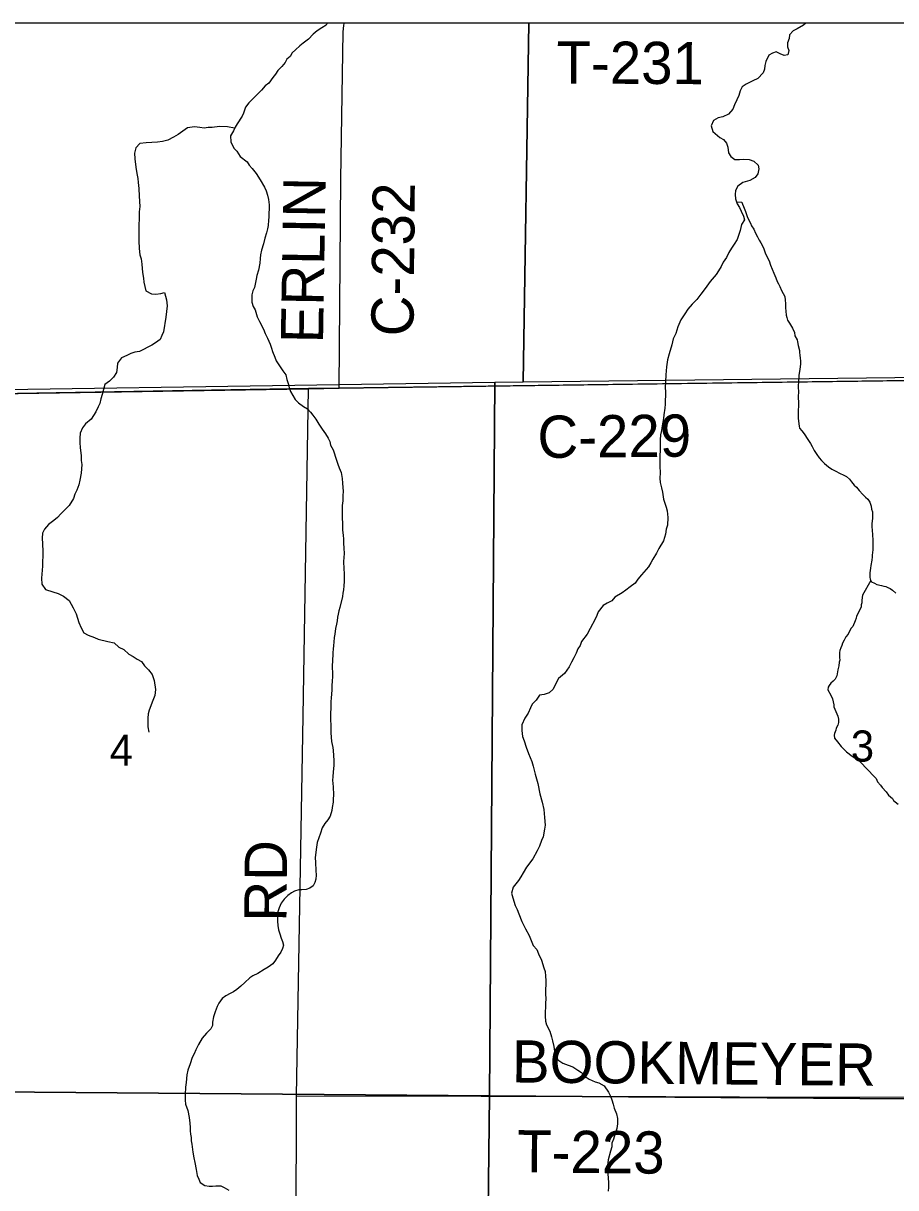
# Model space of a CAD drawing. Extents: x 0 to 34, y 0 to 22.
# Drawn here: x 4.9 to 6.074, y 19.332 to 20.9 of the extents above; entities that cross this region are included whole.
import ezdxf

# ---------------------------------------------------------------- set-up
doc = ezdxf.new("R2010")
doc.units = 0
for name, color, linetype in [('Default', 7, 'Continuous'), ('GM_X_County_Road', 7, 'Continuous'), ('GM_X_County_Road_Text', 7, 'Continuous'), ('GM_X_Minor_River', 7, 'Continuous'), ('GM_X_Section', 7, 'Continuous'), ('GM_X_Section_Text', 7, 'Continuous'), ('GM_X_Township', 7, 'Continuous'), ('GM_X_Township_Road', 7, 'Continuous'), ('GM_X_Township_Road_Text', 7, 'Continuous'), ('SH_Cut_Line', 7, 'Continuous')]:
    doc.layers.add(name, color=color, linetype=linetype)

msp = doc.modelspace()

# ---------------------------------------------------------------- linework, layer by layer
at = {"layer": 'Default'}
for points in [[(5.5805, 20.9), (4.5809, 20.9), (4.5765, 20.4024), (5.5347, 20.4166), (5.573, 20.4171)], [(6.5742, 20.9), (5.5805, 20.9), (5.573, 20.4171), (6.5354, 20.4284), (6.5611, 20.4294)]]:
    msp.add_lwpolyline(points, close=True, dxfattribs=at)
at = {"layer": 'GM_X_County_Road'}
for p, q in [((5.3252, 20.4086), (5.7863, 20.4148)), ((4.5786, 20.3962), (5.2548, 20.4076)), ((5.2548, 20.4076), (5.2842, 20.408)), ((5.2767, 19.9672), (5.2842, 20.408)), ((5.2842, 20.408), (5.3252, 20.4086))]:
    msp.add_line(p, q, dxfattribs=at)
for points in [[(5.3252, 20.4086), (5.3278, 20.69), (5.3306, 20.8882), (5.3315, 20.8973), (5.3319, 20.8992), (5.3321, 20.9)], [(5.7863, 20.4148), (6.5318, 20.4249), (6.5577, 20.4253)], [(5.2631, 18.9836), (5.2634, 18.9924), (5.2647, 19.0793), (5.2659, 19.1795), (5.2671, 19.291), (5.2679, 19.3886), (5.2681, 19.4561), (5.2767, 19.9672)]]:
    msp.add_lwpolyline(points, dxfattribs=at)
at = {"layer": 'GM_X_Minor_River'}
for points in [[(5.3092, 20.9), (5.3078, 20.8975), (5.302, 20.8938), (5.2959, 20.8897), (5.2906, 20.8855), (5.284, 20.8788), (5.2768, 20.8732), (5.2726, 20.8698), (5.2668, 20.8642), (5.2622, 20.86), (5.2595, 20.8551), (5.2549, 20.8518), (5.2526, 20.8472), (5.2483, 20.842), (5.2426, 20.8363), (5.2399, 20.8314), (5.236, 20.8269), (5.2306, 20.8194), (5.226, 20.8156), (5.2207, 20.81), (5.2145, 20.8036), (5.2088, 20.798), (5.2038, 20.7927), (5.1992, 20.7871), (5.1968, 20.7791), (5.1948, 20.775), (5.1879, 20.7648), (5.1852, 20.7603), (5.1832, 20.755), (5.179, 20.7486), (5.1797, 20.7402), (5.1837, 20.7318), (5.1875, 20.7276), (5.192, 20.7207), (5.2017, 20.7134), (5.2043, 20.7088), (5.2085, 20.7046), (5.2137, 20.6977), (5.2189, 20.6893), (5.2249, 20.6794), (5.2271, 20.6744), (5.2289, 20.6687), (5.2304, 20.6626), (5.231, 20.6554), (5.2309, 20.6391), (5.2304, 20.6349), (5.2296, 20.6277), (5.2288, 20.6231), (5.2276, 20.6178), (5.2252, 20.6106), (5.2236, 20.6031), (5.2209, 20.5944), (5.2197, 20.5883), (5.2192, 20.5834), (5.2184, 20.5769), (5.2168, 20.5678), (5.2144, 20.5603), (5.2136, 20.5553), (5.2124, 20.5489), (5.2112, 20.5444), (5.2092, 20.5398), (5.2077, 20.5345), (5.2079, 20.5247), (5.2098, 20.5189), (5.2124, 20.514), (5.2149, 20.5048), (5.2183, 20.4987), (5.2234, 20.488), (5.226, 20.4823), (5.229, 20.4762), (5.2323, 20.4678), (5.2342, 20.4625), (5.2356, 20.4579), (5.2389, 20.4503), (5.2408, 20.4457), (5.2497, 20.432), (5.2538, 20.4266), (5.2549, 20.4205), (5.2571, 20.4137), (5.2582, 20.4091), (5.26, 20.4041), (5.266, 20.3934), (5.2705, 20.3888), (5.2773, 20.3842), (5.2829, 20.3807), (5.287, 20.3765), (5.29, 20.3723), (5.2938, 20.367), (5.2978, 20.3601), (5.3027, 20.3536), (5.3072, 20.3471), (5.3105, 20.3413), (5.3128, 20.3371), (5.3135, 20.3318), (5.3172, 20.3257), (5.322, 20.312), (5.3234, 20.3063), (5.3253, 20.3017)], [(5.9534, 20.9), (5.9504, 20.8974), (5.9416, 20.8926), (5.9362, 20.89), (5.9316, 20.8844), (5.9308, 20.8794), (5.9289, 20.8738), (5.9288, 20.8684), (5.9306, 20.8635), (5.929, 20.8574), (5.9241, 20.8567), (5.9188, 20.8587), (5.9135, 20.8614), (5.9086, 20.8599), (5.9036, 20.857), (5.8997, 20.8486), (5.8982, 20.8433), (5.8977, 20.8384), (5.8958, 20.8331), (5.8889, 20.8256), (5.882, 20.8226), (5.8732, 20.8178), (5.8679, 20.8144), (5.8651, 20.8092), (5.8632, 20.8027), (5.8605, 20.7967), (5.8573, 20.7903), (5.855, 20.7842), (5.8492, 20.7774), (5.8416, 20.7741), (5.8355, 20.7726), (5.829, 20.7693), (5.8259, 20.7617), (5.8281, 20.7541), (5.8375, 20.7464), (5.8428, 20.7437), (5.8465, 20.7384), (5.8483, 20.733), (5.8494, 20.7254), (5.8524, 20.7205), (5.858, 20.7166), (5.8641, 20.7165), (5.8694, 20.7172), (5.877, 20.7164), (5.8834, 20.7144), (5.8894, 20.7091), (5.8901, 20.7041), (5.8889, 20.6973), (5.8854, 20.6924), (5.8782, 20.6883), (5.8687, 20.6854), (5.8618, 20.6809), (5.8587, 20.6748), (5.8582, 20.6695), (5.8589, 20.6638), (5.8611, 20.657), (5.8641, 20.652), (5.8663, 20.647), (5.8697, 20.6402), (5.8708, 20.6352), (5.8669, 20.6292), (5.8649, 20.6209), (5.861, 20.6088), (5.8571, 20.6027), (5.8532, 20.5971), (5.8498, 20.5914), (5.8467, 20.5846), (5.842, 20.5782), (5.8397, 20.5725), (5.8358, 20.5665), (5.8327, 20.5616), (5.8247, 20.5522), (5.8181, 20.5428), (5.812, 20.5353), (5.8066, 20.5281), (5.8004, 20.5217), (5.7947, 20.5153), (5.7904, 20.5089)], [(5.1846, 20.7587), (5.175, 20.7607), (5.1643, 20.7609), (5.1545, 20.7598), (5.1492, 20.7595), (5.1435, 20.7588), (5.1378, 20.7596), (5.1306, 20.7605), (5.1211, 20.7594), (5.115, 20.7546), (5.1088, 20.7504), (5.1023, 20.7467), (5.0947, 20.7426), (5.0875, 20.7408), (5.0807, 20.7401), (5.0731, 20.7394), (5.0655, 20.7391), (5.0571, 20.7381), (5.0517, 20.7321), (5.0501, 20.7253), (5.0504, 20.7177), (5.0518, 20.7063), (5.0532, 20.6979), (5.0543, 20.6911), (5.055, 20.6854), (5.0557, 20.6774), (5.0563, 20.6671), (5.0569, 20.6531), (5.0564, 20.6462), (5.0563, 20.6371), (5.0559, 20.628), (5.0556, 20.6071), (5.0563, 20.5969), (5.0573, 20.5881), (5.0588, 20.5828), (5.0598, 20.5756), (5.0608, 20.5646), (5.0619, 20.557), (5.0626, 20.5513), (5.0636, 20.5456), (5.0651, 20.5399), (5.0726, 20.5356), (5.0787, 20.5352), (5.0852, 20.5362), (5.0905, 20.5377), (5.093, 20.5278), (5.0937, 20.5194), (5.092, 20.5043), (5.0891, 20.4846), (5.0868, 20.4796), (5.0844, 20.4744), (5.0783, 20.4699), (5.0734, 20.4665), (5.0566, 20.4583), (5.0505, 20.4573), (5.0448, 20.4554), (5.0394, 20.4528), (5.0326, 20.4495), (5.0272, 20.4423), (5.0264, 20.4366), (5.0255, 20.4298), (5.0217, 20.4234), (5.0163, 20.4181), (5.0098, 20.4137), (5.0062, 20.4), (5.0046, 20.3944), (5.0034, 20.3883), (5.0011, 20.3834), (4.998, 20.377), (4.9918, 20.3672), (4.9838, 20.3608), (4.9799, 20.3555), (4.9768, 20.348), (4.9763, 20.3415), (4.9763, 20.3354), (4.9766, 20.3286), (4.978, 20.3183), (4.9783, 20.3115), (4.979, 20.3058), (4.9781, 20.2944), (4.9765, 20.2849), (4.9752, 20.2785), (4.9721, 20.2713), (4.9698, 20.266), (4.9678, 20.26), (4.962, 20.2509), (4.9563, 20.2449), (4.9509, 20.2397), (4.9463, 20.2348), (4.9413, 20.2307), (4.934, 20.2254), (4.9287, 20.219), (4.9259, 20.2134), (4.9255, 20.2069), (4.9262, 20.1993), (4.9264, 20.1887), (4.9262, 20.1689), (4.9249, 20.153), (4.9252, 20.1447), (4.93, 20.1378), (4.9402, 20.1346)], [(5.8603, 20.6595), (5.8674, 20.6593), (5.8682, 20.6563), (5.8697, 20.6533), (5.8724, 20.6465), (5.8743, 20.64), (5.8766, 20.6347), (5.8789, 20.6309), (5.8805, 20.6275), (5.8835, 20.6226), (5.8858, 20.6173), (5.8885, 20.6123), (5.8908, 20.6082), (5.8927, 20.6044), (5.895, 20.6002), (5.8969, 20.5964), (5.8989, 20.5911), (5.9016, 20.5851), (5.9039, 20.5801), (5.9058, 20.5744), (5.9081, 20.5691), (5.9104, 20.5634), (5.9131, 20.5574), (5.915, 20.5524), (5.9165, 20.549), (5.9185, 20.5456), (5.9208, 20.5403), (5.9231, 20.5362), (5.925, 20.532), (5.9258, 20.5274), (5.9262, 20.5229), (5.9262, 20.5168), (5.9266, 20.5122), (5.927, 20.5069), (5.9278, 20.5039), (5.9289, 20.5005), (5.9316, 20.4963), (5.9354, 20.4895), (5.9381, 20.4838), (5.9385, 20.4792), (5.9416, 20.4739), (5.942, 20.4713), (5.9432, 20.466), (5.9447, 20.4595), (5.9451, 20.4565), (5.9455, 20.4538), (5.9459, 20.4485), (5.9463, 20.4459), (5.9463, 20.4417), (5.9452, 20.4337), (5.9441, 20.4261), (5.9434, 20.4177), (5.9431, 20.4113), (5.9435, 20.4025), (5.9431, 20.3987), (5.9431, 20.3953), (5.9435, 20.3904), (5.9436, 20.387), (5.9432, 20.3763), (5.9433, 20.368), (5.9445, 20.3577), (5.9449, 20.3547), (5.9479, 20.3513), (5.951, 20.3471), (5.9563, 20.3395), (5.9598, 20.3342), (5.9621, 20.3301), (5.9647, 20.3248), (5.9682, 20.3195), (5.9716, 20.3149), (5.9743, 20.3115), (5.9785, 20.3074), (5.9838, 20.3028), (5.9884, 20.2998), (5.9937, 20.2972), (5.9987, 20.2945), (6.0048, 20.2915), (6.0082, 20.2896), (6.012, 20.2862), (6.0151, 20.2828), (6.0185, 20.2783), (6.0216, 20.2753), (6.0254, 20.2711), (6.03, 20.2658), (6.0338, 20.262), (6.0368, 20.2594), (6.0395, 20.2552), (6.0414, 20.2499), (6.0418, 20.2457), (6.043, 20.2423), (6.043, 20.2332), (6.0423, 20.2267), (6.0423, 20.2222), (6.0427, 20.2176), (6.0431, 20.2112), (6.0436, 20.2043), (6.0436, 20.1914), (6.0433, 20.1869), (6.0429, 20.1842), (6.0429, 20.1815), (6.0422, 20.1774)], [(5.7904, 20.5089), (5.7854, 20.5006), (5.7811, 20.4912), (5.7783, 20.4825), (5.7748, 20.4753), (5.7729, 20.467), (5.7693, 20.4549), (5.7673, 20.4469), (5.7661, 20.4374), (5.7652, 20.4268), (5.7647, 20.4173), (5.7642, 20.4094), (5.7646, 20.4044), (5.7645, 20.398), (5.764, 20.393), (5.764, 20.387), (5.7635, 20.382), (5.7623, 20.3729), (5.7619, 20.368), (5.7611, 20.3631), (5.7599, 20.3582), (5.759, 20.3517), (5.7578, 20.3457), (5.7574, 20.3392), (5.757, 20.3039), (5.7572, 20.2948), (5.7568, 20.2876), (5.7575, 20.2819), (5.7593, 20.2747), (5.7604, 20.2689), (5.7621, 20.2594), (5.7654, 20.2484), (5.7669, 20.2434), (5.7679, 20.2347), (5.7674, 20.2245), (5.7655, 20.2188), (5.7646, 20.2123), (5.7619, 20.2033), (5.7557, 20.1927), (5.7526, 20.1867), (5.7476, 20.1787), (5.7449, 20.1738), (5.7418, 20.1682), (5.7322, 20.1573), (5.7272, 20.1516), (5.7237, 20.1463), (5.7168, 20.1415), (5.7114, 20.1366), (5.7061, 20.1333), (5.6965, 20.1273), (5.6923, 20.1224), (5.6862, 20.1194), (5.6808, 20.1161), (5.6739, 20.1078), (5.672, 20.1025), (5.67, 20.0976), (5.6634, 20.0851), (5.6592, 20.0776), (5.6515, 20.0678), (5.6495, 20.0625), (5.6468, 20.0576), (5.6445, 20.0519), (5.6414, 20.0459), (5.6379, 20.0398), (5.6351, 20.0338), (5.6286, 20.0248), (5.6206, 20.018), (5.6159, 20.0093), (5.6132, 20.0033), (5.6082, 19.9988), (5.6013, 19.9962), (5.5949, 19.9955), (5.5906, 19.9887), (5.5853, 19.9835), (5.5829, 19.9782), (5.5798, 19.971), (5.5752, 19.9646), (5.5713, 19.9555), (5.5712, 19.9479), (5.5722, 19.9399), (5.5745, 19.9339), (5.577, 19.9255), (5.5803, 19.9167), (5.5848, 19.906), (5.5866, 19.8999), (5.5891, 19.8889), (5.5928, 19.8767), (5.5956, 19.8626), (5.5985, 19.8512), (5.6007, 19.8417), (5.6017, 19.8307), (5.6027, 19.8204), (5.6019, 19.8151), (5.5999, 19.8045), (5.5976, 19.7996), (5.5948, 19.792), (5.5917, 19.786), (5.5859, 19.7751), (5.5774, 19.7638), (5.5732, 19.7562), (5.5697, 19.7509)], [(5.3253, 20.3017), (5.3282, 20.2952), (5.3293, 20.2872), (5.3299, 20.2808), (5.3306, 20.2698), (5.3305, 20.2641), (5.3301, 20.2572), (5.3296, 20.2508), (5.3294, 20.2337), (5.3297, 20.2269), (5.33, 20.2178), (5.3307, 20.2105), (5.331, 20.206), (5.3313, 20.1999), (5.3316, 20.1934), (5.3319, 20.1862), (5.3314, 20.1752), (5.3317, 20.1657), (5.332, 20.1593), (5.3323, 20.1543), (5.3322, 20.1486), (5.3318, 20.1426), (5.331, 20.1373), (5.3305, 20.1327), (5.3297, 20.1282), (5.3261, 20.1134), (5.325, 20.1089), (5.3241, 20.1047), (5.3233, 20.1005), (5.3225, 20.0956), (5.3217, 20.0911), (5.3205, 20.0854), (5.3197, 20.0774), (5.3188, 20.0729), (5.318, 20.0668), (5.3176, 20.0623), (5.3172, 20.0573), (5.3167, 20.0528), (5.3167, 20.0486), (5.3163, 20.0444), (5.3161, 20.0323), (5.3164, 20.0258), (5.3164, 20.0201), (5.3159, 20.0148), (5.3155, 20.008), (5.3154, 20.0027), (5.3145, 19.9913), (5.3141, 19.9868), (5.3138, 19.9621), (5.3141, 19.9552), (5.314, 19.9446), (5.315, 19.9332), (5.3168, 19.9252), (5.3175, 19.921), (5.3181, 19.9074), (5.318, 19.9009), (5.3172, 19.8922), (5.3167, 19.8857), (5.3163, 19.8808), (5.317, 19.8763), (5.3173, 19.8721), (5.3176, 19.8614), (5.3171, 19.8554), (5.3171, 19.8512), (5.3159, 19.8444), (5.3154, 19.8402), (5.3131, 19.8326), (5.31, 19.8277), (5.3061, 19.8225), (5.3027, 19.8168), (5.3003, 19.8096), (5.2979, 19.8032), (5.2956, 19.7971), (5.2948, 19.7907), (5.2931, 19.7771), (5.2934, 19.7702), (5.294, 19.7592), (5.2943, 19.7531), (5.2939, 19.7478), (5.2927, 19.7433), (5.2904, 19.7387), (5.2858, 19.7358), (5.2808, 19.7339), (5.2751, 19.7332), (5.271, 19.7333), (5.2653, 19.7318), (5.2611, 19.7292), (5.2561, 19.7258), (5.2515, 19.7209), (5.2472, 19.7153), (5.2445, 19.7093), (5.2429, 19.7036), (5.2425, 19.696), (5.2424, 19.6911), (5.2427, 19.6854), (5.2438, 19.6793), (5.2453, 19.6743), (5.2475, 19.6682), (5.2493, 19.6636), (5.2504, 19.6587), (5.2492, 19.6545)], [(6.0422, 20.1774), (6.0407, 20.1698), (6.0403, 20.1663), (6.0396, 20.1603), (6.0396, 20.1542), (6.04, 20.1515), (6.0419, 20.1481), (6.0457, 20.1462), (6.0492, 20.1443), (6.0552, 20.1432), (6.0583, 20.1421), (6.061, 20.1417), (6.064, 20.1406), (6.067, 20.1391), (6.0701, 20.1369), (6.0747, 20.1327)], [(6.0409, 20.1499), (6.0296, 20.1299), (6.029, 20.1235), (6.0286, 20.1197), (6.0278, 20.117), (6.0277, 20.1144), (6.0261, 20.1102), (6.0218, 20.102), (6.0213, 20.0993), (6.0198, 20.0956), (6.0166, 20.0877), (6.0142, 20.0851), (6.0103, 20.0776), (6.0072, 20.0738), (6.0052, 20.0693), (6.0028, 20.0656), (6.002, 20.0622), (6.0004, 20.0592), (5.9992, 20.0554), (5.9988, 20.0527), (5.9987, 20.0463), (5.999, 20.0425), (5.9985, 20.0399), (5.9977, 20.0349), (5.9964, 20.0297), (5.9951, 20.0213), (5.9931, 20.0172), (5.99, 20.0142), (5.9873, 20.0116), (5.985, 20.0086), (5.9834, 20.006), (5.983, 20.0026), (5.987, 19.9953), (5.9892, 19.9907), (5.9913, 19.9823), (5.9912, 19.9797), (5.9937, 19.9736), (5.9963, 19.9671), (5.9973, 19.9633), (5.9976, 19.9587), (5.9964, 19.9549), (5.9944, 19.9508), (5.9936, 19.9482), (5.992, 19.944), (5.9916, 19.9414), (5.9922, 19.9376), (5.9959, 19.9326), (6.0011, 19.9264), (6.0081, 19.919), (6.016, 19.9132), (6.0249, 19.9077), (6.0383, 19.8938), (6.0434, 19.8876), (6.0479, 19.8833), (6.0497, 19.8788), (6.0538, 19.8745), (6.056, 19.871), (6.0615, 19.8652), (6.0648, 19.861), (6.07, 19.8563), (6.0715, 19.8537), (6.0775, 19.8486)], [(4.9402, 20.1346), (4.947, 20.1323), (4.9542, 20.1288), (4.9621, 20.123), (4.9673, 20.1131), (4.9714, 20.1051), (4.975, 20.0933), (4.978, 20.086), (4.9817, 20.0795), (4.9877, 20.076), (4.996, 20.0733), (5.0009, 20.071), (5.0142, 20.0678), (5.0225, 20.0658), (5.0289, 20.06), (5.0357, 20.0569), (5.0424, 20.0508), (5.0481, 20.0477), (5.0534, 20.0438), (5.0594, 20.0407), (5.0635, 20.035), (5.0688, 20.0296), (5.0736, 20.0231), (5.0762, 20.0151), (5.0783, 20.0029), (5.0771, 19.995), (5.0739, 19.9859), (5.072, 19.981), (5.0697, 19.9753), (5.0685, 19.9704), (5.068, 19.9643), (5.0679, 19.9526), (5.0691, 19.9456)], [(5.5697, 19.7509), (5.5666, 19.746), (5.5597, 19.737), (5.5573, 19.7291), (5.5591, 19.7226), (5.5621, 19.7123), (5.565, 19.707), (5.5672, 19.7009), (5.5713, 19.6909), (5.5761, 19.681), (5.5809, 19.6719), (5.5839, 19.665), (5.5865, 19.6585), (5.5913, 19.6531), (5.5936, 19.647), (5.5976, 19.6387), (5.6006, 19.6284), (5.6024, 19.6234), (5.6031, 19.617), (5.6034, 19.6113), (5.6032, 19.5938), (5.6035, 19.5862), (5.603, 19.5813), (5.6028, 19.5634), (5.6031, 19.5566), (5.6046, 19.5517), (5.6091, 19.5429), (5.6112, 19.5353), (5.6123, 19.5303), (5.6145, 19.5223), (5.6152, 19.5162), (5.6155, 19.5109), (5.6196, 19.5044), (5.6264, 19.4998), (5.6336, 19.4974), (5.64, 19.4951), (5.6464, 19.4905), (5.6517, 19.4874), (5.6565, 19.482), (5.6618, 19.4785), (5.6701, 19.4747), (5.675, 19.4735), (5.6818, 19.4696), (5.6878, 19.4608), (5.6904, 19.4558), (5.6922, 19.4505), (5.694, 19.4448), (5.6955, 19.4395), (5.6988, 19.4318), (5.6999, 19.4254), (5.6998, 19.4185), (5.699, 19.4121), (5.6966, 19.4041), (5.6946, 19.3977), (5.6923, 19.3924), (5.6922, 19.3875), (5.6907, 19.3814), (5.6875, 19.3697), (5.6863, 19.3621), (5.6866, 19.356), (5.6869, 19.3511), (5.6879, 19.3393), (5.6878, 19.3333), (5.6874, 19.3276)], [(5.2492, 19.6545), (5.2469, 19.6496), (5.2434, 19.6447), (5.2399, 19.6387), (5.2361, 19.6338), (5.23, 19.6293), (5.2246, 19.626), (5.2158, 19.6207), (5.2093, 19.6178), (5.2051, 19.6148), (5.1986, 19.6088), (5.1932, 19.6039), (5.1875, 19.599), (5.1833, 19.596), (5.1787, 19.5938), (5.173, 19.5908), (5.168, 19.5871), (5.1634, 19.5807), (5.1611, 19.5765), (5.1587, 19.5693), (5.1564, 19.5625), (5.1551, 19.5553), (5.1551, 19.5508), (5.1528, 19.5463), (5.147, 19.5402), (5.1408, 19.5335), (5.1362, 19.5252), (5.1323, 19.518), (5.1304, 19.5127), (5.1277, 19.5078), (5.1249, 19.4991), (5.1218, 19.4908), (5.1202, 19.4843), (5.1193, 19.4741), (5.1185, 19.4677), (5.118, 19.4578), (5.1179, 19.4502), (5.1186, 19.4449), (5.1215, 19.4361), (5.1237, 19.427), (5.1244, 19.4194), (5.1247, 19.4133), (5.125, 19.4091), (5.1253, 19.4046), (5.126, 19.4), (5.1264, 19.3955), (5.1271, 19.3909), (5.1285, 19.3803), (5.1299, 19.3726), (5.131, 19.3662), (5.1328, 19.3567), (5.1342, 19.3487), (5.1364, 19.3437), (5.1383, 19.3395), (5.1447, 19.3353), (5.1503, 19.3345), (5.1549, 19.3344), (5.1594, 19.3347), (5.1659, 19.3351), (5.1708, 19.3327), (5.1768, 19.3289)]]:
    msp.add_lwpolyline(points, dxfattribs=at)
at = {"layer": 'GM_X_Section'}
for points in [[(6.5354, 20.4284), (6.5246, 19.4487), (5.5276, 19.4562), (5.5347, 20.4166), (5.573, 20.4171)], [(5.5347, 20.4166), (5.5276, 19.4562), (4.5252, 19.4639), (4.5401, 20.4008), (4.5765, 20.4024)], [(5.5276, 19.4562), (5.5161, 18.4568), (4.517, 18.4555), (4.5252, 19.4639)], [(6.5246, 19.4487), (6.5078, 18.4687), (5.5161, 18.4568), (5.5276, 19.4562)]]:
    msp.add_lwpolyline(points, close=True, dxfattribs=at)
at = {"layer": 'GM_X_Township'}
msp.add_lwpolyline([(4.5784, 20.3968), (5.284, 20.4086), (5.325, 20.4092), (6.5316, 20.4254), (6.5575, 20.4259), (7.5409, 20.4415), (8.556, 20.4544), (8.5437, 19.4556), (8.5436, 19.4447), (8.5388, 18.7451), (8.5216, 17.7888), (8.5215, 17.7806), (8.5214, 17.7731), (8.5094, 16.832), (8.5093, 16.83), (8.4947, 15.4259), (8.4895, 15.0042)], dxfattribs=at)
at = {"layer": 'GM_X_Township_Road'}
for p, q in [((5.2681, 19.4561), (5.7648, 19.455)), ((5.7648, 19.455), (5.864, 19.4548)), ((5.864, 19.4548), (6.5287, 19.4533))]:
    msp.add_line(p, q, dxfattribs=at)
msp.add_lwpolyline([(4.5784, 20.3968), (5.284, 20.4086), (5.325, 20.4092), (6.5316, 20.4254), (6.5575, 20.4259), (7.5409, 20.4415), (8.556, 20.4544), (8.5676, 20.9), (2.6262, 20.9)], dxfattribs=at)
at = {"layer": 'SH_Cut_Line'}
msp.add_lwpolyline([(8.9, 14.4215), (8.9, 20.9), (2.1, 20.9)], dxfattribs=at)

# ---------------------------------------------------------------- texts
at = {"layer": 'GM_X_County_Road_Text'}
for s, rotation, p in [('ERLIN', 89.0651, (5.3036, 20.4688)), ('C-232', 89.4494, (5.4253, 20.4783)), ('C-229', 0.5511, (5.5925, 20.3147)), ('RD', 89.5063, (5.2544, 19.6903))]:
    msp.add_text(s, height=0.05682, rotation=rotation, dxfattribs=at).set_placement(p)
at = {"layer": 'GM_X_Section_Text'}
for s, p in [('4', (5.0166, 19.9004)), ('3', (6.0141, 19.906))]:
    msp.add_text(s, height=0.0419, rotation=0, dxfattribs=at).set_placement(p)
at = {"layer": 'GM_X_Township_Road_Text'}
for s, rotation, p in [('T-231', 359.7193, (5.6177, 20.8189)), ('BOOKMEYER', 359.4573, (5.5577, 19.4741)), ('T-223', 359.4381, (5.5647, 19.3531))]:
    msp.add_text(s, height=0.05682, rotation=rotation, dxfattribs=at).set_placement(p)

doc.saveas('drawing.dxf')
